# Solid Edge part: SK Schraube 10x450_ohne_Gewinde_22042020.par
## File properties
Author: fknapp
Template: Normal.par
Last saved by: fknapp
Revision: 34
Application: Solid Edge
Username: fknapp
Material: Aluminium
Genauigkeit: 0,99
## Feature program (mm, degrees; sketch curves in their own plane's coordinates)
sketch for "unnamed RevolvedProtrusion 1" plane through (0, 0, 0) normal (0, 0, 1) x-axis (1, 0, 0)
  line (0, 54) -> (9, 54)
  line (9, 54) -> (9, 53)
  line (9, 53) -> (5, 49)
  line (5, 49) -> (5, 46.3)
  line (5, 46.3) -> (4.7548, 46.3)
  arc centre (4.7548, 44.6952) radius 1.6048 from (4.7548, 46.3) to (3.15, 44.6952) ccw
  line (3.15, 44.6952) -> (3.15, 42)
  line (3.15, 42) -> (5, 42)
  line (5, -383) -> (5, 42)
  line (0.5, -396) -> (5, -383)
  line (0, -396) -> (0.5, -396)
revolve "unnamed RevolvedProtrusion 1" add full turn 360 deg about sketch line (0, 54) -> (0, -396)
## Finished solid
Body 1: solid body, 11 faces, 10 edges, 0 vertices.
  Faces by surface: cylinder 4, plane 4, cone 2, torus 1
  Edges by curve: circle 10
Bounding box of the edges (mm; curved faces can reach further): 18.000 x 450.000 x 18.000, from (-9, -396, -9) to (9, 54, 9).
Cylindrical faces by radius (mm): R3.15 x1, R5 x2, R9 x1
Conical faces (half-angle, radius in mm at the cone's reference point): 19.0935 deg R5 x1, 45 deg R9 x1
Toroidal faces (ring radius, tube radius in mm): R4.7548 r1.6048 x1
Planar faces by outward normal: +y 2, -y 2
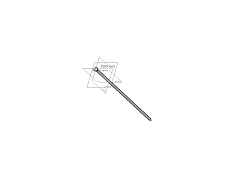
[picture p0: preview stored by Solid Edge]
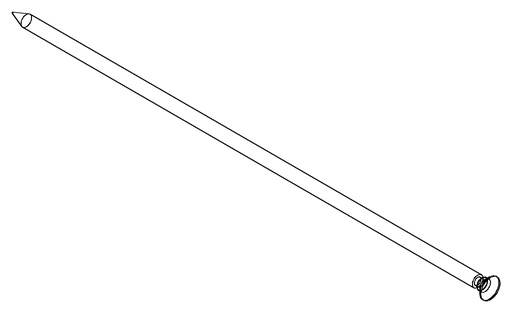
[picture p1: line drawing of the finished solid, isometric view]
